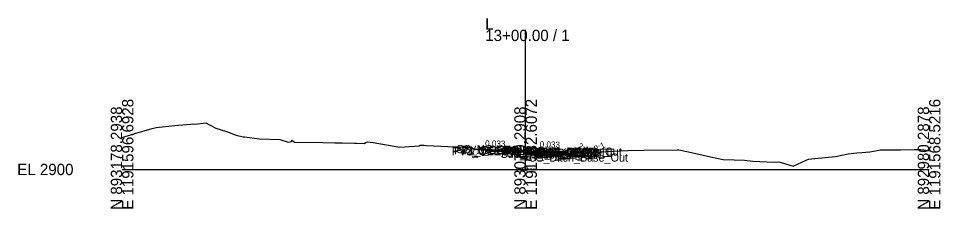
# Model space of a CAD drawing. Extents: x -26 to 203, y -10 to 7027.
# Drawn here: x -25.7 to 202.8, y 5990.3 to 6037.4 of the extents above; entities that cross this region are included whole.
import ezdxf

# ---------------------------------------------------------------- set-up
doc = ezdxf.new("R2010")
doc.units = 0
for name, color, linetype in [('Default', 7, 'Continuous'), ('Exist CMT Pavement', 7, 'Continuous'), ('Exist Cross Section Cell', 7, 'Continuous'), ('Exist XS Center Line Elevation Label', 7, 'Continuous'), ('Exist XS Ground Line', 7, 'Continuous'), ('Prop CMT Concrete Structures', 7, 'Continuous'), ('Prop CMT Pvmt Course 1', 7, 'Continuous'), ('Prop CMT Pvmt Course 2', 7, 'Continuous'), ('Prop CMT Pvmt Course 2 Wedge', 7, 'Continuous'), ('Prop CMT Pvmt Course 3', 7, 'Continuous'), ('Prop CMT Pvmt Course 3 Wedge', 7, 'Continuous'), ('Prop CMT Pvmt Surface', 7, 'Continuous'), ('Prop CMT Pvmt Surface Shoulder', 7, 'Continuous'), ('Prop CMT Pvmt Wedge Surface 3', 7, 'Continuous'), ('Prop CMT Shld Paved Course 1', 7, 'Continuous'), ('Prop CMT Shld Paved Course 2', 7, 'Continuous'), ('Prop CMT Shld Paved Course 3', 7, 'Continuous'), ('Prop CMT Slope Grass', 7, 'Continuous'), ('Prop CMT Subgrade Earthwork', 7, 'Continuous'), ('Scratch_Level_6', 7, 'Continuous')]:
    doc.layers.add(name, color=color, linetype=linetype)

msp = doc.modelspace()

# ---------------------------------------------------------------- linework, layer by layer
at = {"layer": 'Exist CMT Pavement'}
for points in [[(109.7, 6004.21), (110.32, 6004.2), (110.53, 6003.98)], [(109.7, 6004), (109.7, 6004.21)], [(110.53, 6003.98), (109.7, 6004)]]:
    msp.add_lwpolyline(points, dxfattribs=at)
at = {"layer": 'Exist Cross Section Cell'}
for p, q in [((100, 6000), (100, 6034.62)), ((0, 6000), (100, 6000)), ((100, 6000), (200, 6000))]:
    msp.add_line(p, q, dxfattribs=at)
at = {"layer": 'Exist XS Center Line Elevation Label'}
msp.add_lwpolyline([(100, 6004.4), (91.63, 6004.68)], dxfattribs=at)
at = {"layer": 'Exist XS Ground Line'}
msp.add_lwpolyline([(100, 6004.48), (91.63, 6004.76)], dxfattribs=at)
at = {"layer": 'Prop CMT Concrete Structures'}
for points in [[(91.63, 6004.89), (87.1, 6005.04)], [(100, 6004.61), (91.63, 6004.89)], [(100, 6004.61), (109.7, 6004.42)]]:
    msp.add_lwpolyline(points, dxfattribs=at)
at = {"layer": 'Prop CMT Pvmt Course 1'}
for points in [[(100, 6004.61), (91.63, 6004.89)], [(91.63, 6004.89), (91.63, 6004.76)], [(91.63, 6004.76), (100, 6004.48)], [(100, 6004.48), (100, 6004.61)], [(100, 6004.61), (109.7, 6004.42)], [(100, 6004.4), (100, 6004.61)], [(109.7, 6004.21), (100, 6004.4)], [(100, 6004.19), (100, 6004.4)], [(100, 6004.4), (109.7, 6004.21)], [(109.7, 6004), (100, 6004.19)], [(109.7, 6004.42), (109.7, 6004.21)], [(109.7, 6004.21), (109.7, 6004)]]:
    msp.add_lwpolyline(points, dxfattribs=at)
at = {"layer": 'Prop CMT Pvmt Course 2'}
msp.add_lwpolyline([(100, 6004.19), (91.63, 6004.47)], dxfattribs=at)
at = {"layer": 'Prop CMT Pvmt Course 3'}
for points in [[(100, 6004.19), (109.7, 6004)], [(100, 6003.86), (100, 6004.19)], [(109.7, 6003.67), (100, 6003.86)], [(109.7, 6004), (109.7, 6003.67)]]:
    msp.add_lwpolyline(points, dxfattribs=at)
at = {"layer": 'Prop CMT Pvmt Course 3 Wedge'}
for p, q in [((8.4, 6010.36), (12.95, 6010.87)), ((12.95, 6010.87), (13.94, 6011)), ((13.94, 6011), (16.94, 6011.24)), ((16.94, 6011.24), (17.35, 6011.27)), ((17.35, 6011.27), (18, 6011.25)), ((18, 6011.25), (20.73, 6011.54)), ((20.73, 6011.54), (23.26, 6010.25)), ((0.52, 6008.11), (3.16, 6008.87)), ((3.16, 6008.87), (7.47, 6010.16)), ((7.47, 6010.16), (8.4, 6010.36)), ((23.26, 6010.25), (25.91, 6009.38)), ((25.91, 6009.38), (28.23, 6008.49)), ((28.23, 6008.49), (29.97, 6008.09)), ((0, 6007.95), (0.52, 6008.11)), ((29.97, 6008.09), (30.34, 6008.06)), ((30.34, 6008.06), (34.05, 6007.58)), ((34.05, 6007.58), (39.08, 6007.4)), ((39.08, 6007.4), (40.94, 6006.87)), ((40.94, 6006.87), (41.33, 6006.77)), ((41.33, 6006.77), (41.97, 6006.89)), ((41.97, 6006.89), (42.05, 6007.22)), ((42.05, 6007.22), (42.73, 6006.73)), ((42.73, 6006.73), (49.78, 6006.64)), ((49.78, 6006.64), (52.74, 6006.6)), ((52.74, 6006.6), (54.63, 6006.57)), ((54.63, 6006.57), (57.59, 6006.51)), ((57.59, 6006.51), (58.13, 6006.51)), ((58.13, 6006.51), (59.99, 6006.46)), ((59.99, 6006.46), (60.4, 6006.67)), ((60.4, 6006.67), (60.82, 6006.88)), ((60.82, 6006.88), (62.18, 6006.7)), ((62.18, 6006.7), (68.84, 6005.49)), ((68.84, 6005.49), (73.65, 6005.86)), ((73.65, 6005.86), (73.88, 6006.04)), ((73.88, 6006.04), (74.29, 6006.01)), ((74.29, 6006.01), (74.88, 6005.98)), ((74.88, 6005.98), (75.47, 6005.94)), ((75.47, 6005.94), (84.29, 6005.56)), ((84.29, 6005.56), (84.97, 6005.5)), ((84.97, 6005.5), (85.53, 6005.46)), ((85.53, 6005.46), (86.78, 6005.36)), ((86.78, 6005.36), (87.14, 6005)), ((87.14, 6005), (89.28, 6004.83)), ((89.28, 6004.83), (91.38, 6004.67)), ((91.38, 6004.67), (98.48, 6004.41)), ((98.48, 6004.41), (100, 6004.36)), ((100, 6004.36), (100.77, 6004.33)), ((100.77, 6004.33), (102.55, 6004.24)), ((102.55, 6004.24), (109.5, 6003.85)), ((109.5, 6003.85), (112.09, 6003.66)), ((112.09, 6003.66), (113.04, 6003.57)), ((113.04, 6003.57), (116.7, 6004.22)), ((116.7, 6004.22), (117.38, 6004.34)), ((117.38, 6004.34), (118.16, 6004.38)), ((118.16, 6004.38), (125.3, 6004.66)), ((125.3, 6004.66), (129.28, 6004.79)), ((129.28, 6004.79), (137.61, 6004.9)), ((137.61, 6004.9), (137.95, 6004.9)), ((137.95, 6004.9), (140.35, 6004.36)), ((140.35, 6004.36), (145.81, 6003.16)), ((176.77, 6003.17), (179.92, 6003.84)), ((179.92, 6003.84), (182.13, 6004.1)), ((182.13, 6004.1), (183.37, 6004.22)), ((183.37, 6004.22), (185.3, 6004.35)), ((185.3, 6004.35), (187.14, 6004.7)), ((187.14, 6004.7), (187.86, 6004.85)), ((187.86, 6004.85), (190.45, 6004.87)), ((190.45, 6004.87), (192.9, 6004.89)), ((192.9, 6004.89), (196.42, 6004.92)), ((196.42, 6004.92), (197.83, 6004.93)), ((197.83, 6004.93), (198.66, 6004.82)), ((198.66, 6004.82), (200, 6004.63)), ((145.81, 6003.16), (148.97, 6002.44)), ((148.97, 6002.44), (151.69, 6002.35)), ((151.69, 6002.35), (154.26, 6002.29)), ((154.26, 6002.29), (156.35, 6002.06)), ((156.35, 6002.06), (161.62, 6001.8)), ((161.62, 6001.8), (162.79, 6001.9)), ((162.79, 6001.9), (163.33, 6001.72)), ((163.33, 6001.72), (166.3, 6000.82)), ((166.3, 6000.82), (169.52, 6002.28)), ((169.52, 6002.28), (170.14, 6002.56)), ((170.14, 6002.56), (170.88, 6002.6)), ((170.88, 6002.6), (176.77, 6003.17))]:
    msp.add_line(p, q, dxfattribs=at)
at = {"layer": 'Prop CMT Pvmt Surface'}
msp.add_lwpolyline([(110.1, 6004.41), (113.7, 6004.12), (116.06, 6002.94), (119.02, 6004.42)], dxfattribs=at)
at = {"layer": 'Prop CMT Pvmt Surface Shoulder'}
msp.add_lwpolyline([(109.7, 6004.42), (110.1, 6004.41)], dxfattribs=at)
at = {"layer": 'Prop CMT Shld Paved Course 1'}
for points in [[(91.63, 6004.76), (91.63, 6004.89)], [(100, 6004.48), (91.63, 6004.76)], [(100, 6004.48), (100, 6004.61)], [(109.7, 6004.42), (110.1, 6004.41), (110.32, 6004.2)], [(109.7, 6004.21), (109.7, 6004.42)], [(110.32, 6004.2), (109.7, 6004.21)]]:
    msp.add_lwpolyline(points, dxfattribs=at)
at = {"layer": 'Prop CMT Shld Paved Course 2'}
for points in [[(91.63, 6004.68), (91.63, 6004.89)], [(100, 6004.4), (91.63, 6004.68)], [(100, 6004.4), (100, 6004.61)]]:
    msp.add_lwpolyline(points, dxfattribs=at)
at = {"layer": 'Prop CMT Shld Paved Course 3'}
for points in [[(91.63, 6004.47), (91.63, 6004.89)], [(100, 6004.19), (91.63, 6004.47)], [(100, 6004.19), (100, 6004.61)]]:
    msp.add_lwpolyline(points, dxfattribs=at)
at = {"layer": 'Prop CMT Slope Grass'}
for points in [[(109.7, 6004), (110.53, 6003.98), (111.03, 6003.97), (111.37, 6003.63)], [(109.7, 6003.67), (109.7, 6004)], [(111.37, 6003.63), (109.7, 6003.67)]]:
    msp.add_lwpolyline(points, dxfattribs=at)
at = {"layer": 'Prop CMT Subgrade Earthwork'}
for points in [[(100, 6003.86), (109.7, 6003.67)], [(109.7, 6003.67), (111.37, 6003.63)], [(111.37, 6003.63), (111.99, 6004.26)]]:
    msp.add_lwpolyline(points, dxfattribs=at)

# ---------------------------------------------------------------- texts
at = {"layer": 'Default'}
msp.add_text('-', height=0.0001, dxfattribs=at).set_placement((0, 6000))
at = {"layer": 'Exist Cross Section Cell'}
for s, p in [('L', (90, 6034.62)), ('13+00.00 / 1', (90, 6031.82)), ('EL 2900', (-26, 5998.6))]:
    msp.add_text(s, height=2.8, dxfattribs=at).set_placement(p)
for s, p in [('E 1191596.6928', (2.8, 5990)), ('E 1191582.6072', (102.8, 5990)), ('E 1191568.5216', (202.8, 5990)), ('N 893178.2938', (0, 5990)), ('N 893079.2908', (100, 5990)), ('N 892980.2878', (200, 5990))]:
    msp.add_text(s, height=2.8, rotation=90, dxfattribs=at).set_placement(p)
at = {"layer": 'Prop CMT Pvmt Course 2 Wedge'}
for s, p in [('SS_HC', (82.88, 6004.04)), ('PV1_OEEOP', (84.2, 6003.89)), ('PV2_OEEOP_W', (81.74, 6003.68)), ('PV3_OEEOP_W', (81.74, 6003.47)), ('PV1_OEEOP_W', (82.31, 6003.76)), ('PV1_PGL_W', (92.58, 6003.48)), ('Sub_PGL', (93.81, 6002.86)), ('PV2_PGL', (93.91, 6003.4)), ('PV3_PGL', (93.91, 6003.19)), ('PV1_PGL', (94.47, 6003.61)), ('Sub_Trench_Out_DLT', (95.12, 6003.12)), ('Sub_Trench_Out', (98.27, 6002.63)), ('PS3_Shelf_Out', (99.71, 6002.97)), ('SS_Ditch_Base_Out', (100.84, 6001.94)), ('Sub_OEOT', (102.48, 6002.67)), ('PV2_OEOT', (102.57, 6003.21)), ('PV3_OEOT', (102.57, 6003)), ('PV1_OEOT', (103.14, 6003.42)), ('PS2_OEOP', (103.25, 6003.2)), ('PS3_OEOP', (103.46, 6002.98)), ('PS1_OEOP', (103.6, 6003.41)), ('GS_OS_CTL', (105.77, 6003.12)), ('Slope_Cut', (111.35, 6003.42))]:
    msp.add_text(s, height=2, dxfattribs=at).set_placement(p)
at = {"layer": 'Prop CMT Pvmt Surface Shoulder'}
for p in [(89.95, 6005.73), (103.48, 6005.49)]:
    msp.add_text('0.033', height=1.5, rotation=358.8542, dxfattribs=at).set_placement(p)
at = {"layer": 'Prop CMT Pvmt Wedge Surface 3'}
for rotation, p in [(333.4349, (112.79, 6005.33)), (26.5651, (117.4, 6004.27))]:
    msp.add_text('2:1', height=1.5, rotation=rotation, dxfattribs=at).set_placement(p)
at = {"layer": 'Scratch_Level_6'}
msp.add_text('2904.36', height=1, dxfattribs=at).set_placement((97.51, 5999.36))

doc.saveas('drawing.dxf')
